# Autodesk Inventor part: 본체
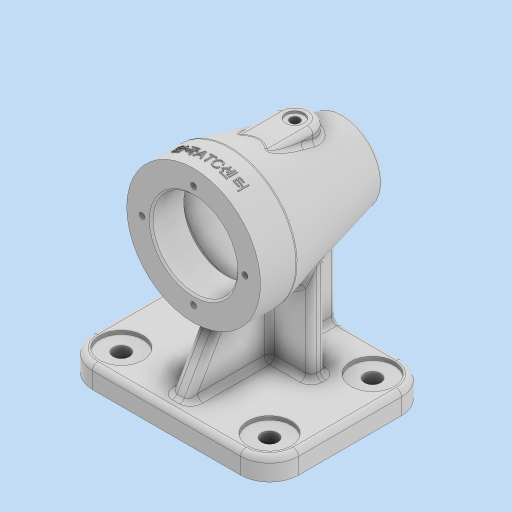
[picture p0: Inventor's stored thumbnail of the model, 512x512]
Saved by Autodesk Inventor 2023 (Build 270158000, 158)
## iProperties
Created: 2024-12
Part Number: 본체
Material: 일반
Document SubType Name: Modeling
Designer: asung
Density: 1 g/cm^3
Appearance: 기본값
Author: asung
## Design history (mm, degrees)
sketch "스케치1"
  geometry: L1 (-5744.5, -45.233)-(-5744.5, 45.233); L2 (5744.5, 45.233)-(5744.5, -45.233); L3 (41, -44.5)-(-41, -44.5); L4 (-57, -28.5)-(-57, 28.5); L5 (-41, 44.5)-(41, 44.5); L6 (57, 28.5)-(57, -28.5); L7 (57, -44.5)-(-57, 44.5); L8 (-57, -44.5)-(57, 44.5); A1 r 16 centre (41, -28.5) between (41, -44.5) and (57, -28.5); A2 r 16 centre (-41, -28.5) between (-57, -28.5) and (-41, -44.5); A3 r 16 centre (-41, 28.5) between (-41, 44.5) and (-57, 28.5); A4 r 16 centre (41, 28.5) between (57, 28.5) and (41, 44.5); 1 further point
  constraints: 16 end point, 8 point on circle, 8 point on line, 8 tangent, 4 centre point, 3 equal radius, 3 parallel, 2 midpoint, 1 horizontal, 1 perpendicular
  dimensions: "d1" = 114 distance of L7.end L8.end; "d2" = 89 distance of L8.start L7.end; "d3" = 16 radius of A1
extrude "돌출1" new body sketch "스케치1" distance "d4" = 12; taper "d5" = 0 deg
sketch "스케치2"
  geometry: A1 r 16 centre (41, -28.5) between (41, -44.5) and (57, -28.5) reference; A2 r 16 centre (41, 28.5) between (57, 28.5) and (41, 44.5) reference; A3 r 16 centre (-41, 28.5) between (-41, 44.5) and (-57, 28.5) reference; A4 r 16 centre (-41, -28.5) between (-57, -28.5) and (-41, -44.5) reference; 1 further point
hole "구멍1" sketch "스케치2" at (-41, 28.5), (-41, -28.5), (41, -28.5), (41, 28.5) diameter "d6" = 9; stored, may be unused: countersink angle "d10" = 90 deg, drill point angle "d12" = 0 deg; dims "d7" = 6, "d8" = 24, "d9" = 2, "d11" = 12
node "작업 평면1"
sketch "스케치4"
  geometry: L1 (73, 12)-(73, 0) reference; L2 (73, 0)-(-16, 0) reference; L3 (-16, 0)-(-16, 12) reference; L4 (-16, 12)-(73, 12) reference; L5 (73, 0)-(57, 0) reference; L6 (58, 82)-(58, 0); L7 (58, 82)-(-26, 82); L8 (-26, 82)-(-26, 103); L9 (58, 82)-(58, 119); L10 (58, 119)-(38, 119); L11 (38, 119)-(-26, 103); 1 further point
  constraints: 12 end point, 3 vertical, 2 horizontal
  dimensions: "d23" = 82 distance of L6.start L6.end; "d24" = 15 distance of L1.end L6.end; "d25" = 0 vertical distance of L1.end L6.end; "d26" = 84 distance of L6.start L7.end; "d29" = 37 distance of L6.start L9.end; "d30" = 20 distance of L9.end L10.end; "d118" = 42 diameter of L8.end L7
revolve "회전1" sketch "스케치4" stored, may be unused: angle "d32" = 90 deg
node "작업 평면2"
sketch "스케치5"
  geometry: L1 (-16.733, 29.5)-(16.733, 29.5) reference; L2 (16.733, 29.5)-(16.733, 9.5) reference; L3 (-16.733, 9.5)-(-16.733, 29.5) reference; L4 (-21, -54.5)-(21, -54.5) reference; L5 (-37, 9.5)-(37, 9.5) reference; L6 (-37, 9.5)-(37, 9.5) reference; L7 (-37, 29.5)-(37, 29.5) reference; L8 (-37, 29.5)-(37, 29.5) reference; L9 (0, 29.5)-(0, -26.5); L10 (10, -26.5)-(10, 4.324); L11 (-10, -26.5)-(-10, 7.832); L12 (-10, 7.832)-(10, 7.832); L13 (10, 7.832)-(10, 4.324); A1 r 10 centre (0, -26.5) between (10, -26.5) and (-10, -26.5); 3 further points
  constraints: 10 end point, 2 perpendicular, 2 point on circle, 2 tangent, 2 vertical, 1 centre point, 1 coincident, 1 midpoint, 1 parallel, 1 point on line, 1 other
  dimensions: "d35" = 56 distance of L9.start L9.end; "d36" = 20 diameter of A1
extrude "돌출2" join sketch "스케치5" stored distance "d37" = 12; taper "d38" = 0 deg
sketch "스케치6"
  geometry: L1 (58, 119)-(58, 45) reference; L2 (58, 45)-(38, 45) reference; L3 (38, 45)-(-26, 61) reference; L4 (-26, 61)-(-26, 103) reference; L5 (-26, 103)-(-8, 107.5) reference; L6 (-8, 107.5)-(-8, 115) reference; L7 (-8, 115)-(22, 115) reference; L8 (22, 115)-(38, 119) reference; L9 (38, 119)-(58, 119) reference; L10 (-16, 0)-(-16, 12) reference; L11 (-16, 12)-(73, 12) reference; L12 (73, 12)-(73, 0) reference; L13 (73, 0)-(-16, 0) reference; L14 (-16, 0)-(-16, 12) reference; L15 (-16, 12)-(-16, 65.487); L16 (35.119, 65.487)-(66, 12); L17 (58, 119)-(58, 45) reference; L18 (-26, 61)-(-26, 103) reference; L19 (-26, 103)-(-8, 107.5) reference; L20 (-8, 107.5)-(-8, 115) reference; L21 (-8, 115)-(22, 115) reference; L22 (38, 119)-(58, 119) reference; L23 (-16, 0)-(-16, 12) reference; L24 (-16, 12)-(73, 12) reference; L25 (73, 12)-(73, 0) reference; L26 (73, 0)-(-16, 0) reference; L27 (-16, 65.487)-(35.119, 65.487); L28 (22, 115)-(38, 119) reference; 2 further points; 2 other entities
  constraints: 6 end point, 1 horizontal, 1 point on line, 1 vertical, 2 other
  dimensions: "d39" = 7 distance from line of L12 L16.end; "d40" = 60 deg angle of L11 L16; "d41" = 65.48678 distance between parallel lines of L13 L27
extrude "돌출3" join sketch "스케치6" stored distance "d42" = 10; taper "d43" = 0 deg
node "작업 평면3"
sketch "스케치7"
  geometry: L1 (51, 115)-(51, 111.079) reference; L2 (46, 51.659)-(46, 12) reference; L3 (46, 12)-(98, 12) reference; L4 (98, 12)-(98, 0) reference; L5 (98, 0)-(-16, 0) reference; L6 (-16, 0)-(-16, 12) reference; L7 (-16, 12)-(36, 12) reference; L8 (36, 12)-(36, 51.659) reference; L9 (31, 111.079)-(31, 115) reference; L10 (31, 115)-(51, 115) reference; L11 (69, 69.289)-(69, 12); L12 (13, 69.289)-(13, 12); A1 r 30.75 centre (41, 82) between (46, 51.659) and (51, 111.079) reference; A2 r 30.75 centre (41, 82) between (31, 111.079) and (36, 51.659) reference; 1 further point
  constraints: 4 end point, 2 point on circle, 2 point on line, 2 vertical
  dimensions: "d45" = 56 distance of L12.end L11.end; "d46" = 28 horizontal distance of point (41, 0) L11.end
  node "절단 모서리 투영5"
feature "리브1" dims "d47" = 1, "d48" = 8, "d49" = 0, "d50" = 0, "d51" = 1, "d52" = 1
feature "리브2" dims "d53" = 1, "d54" = 8, "d55" = 0, "d56" = 0, "d57" = 1, "d58" = 1
sketch "스케치8"
  geometry: C1 r 37 at (0, 0) reference; 2 further points
  constraints: 1 coincident
hole "구멍2" sketch "스케치8" at (0, 0) diameter "d59" = 47; stored, may be unused: countersink angle "d63" = 90 deg, drill point angle "d65" = 0 deg; dims "d60" = 6, "d61" = 24, "d62" = 2, "d64" = 18
chamfer "모따기1" distance "d66" = 1; stored, may be unused: second distance "d67" = 2, angle "d68" = 45 deg
sketch "스케치9"
  geometry: L1 (61, -54.5)-(58.5, -44.5) reference; L2 (58.5, -44.5)-(0, -44.5) reference; L3 (0, -44.5)-(0, 44.5) reference; L4 (0, 44.5)-(12, 44.5) reference; L5 (12, 44.5)-(12, 37.5) reference; L6 (12, 37.5)-(45, 18.447) reference; L7 (45, 18.447)-(45, 29.5) reference; L8 (45, 29.5)-(57.5, 29.5) reference; L9 (57.5, 29.5)-(58.5, 28.5) reference; L10 (58.5, 28.5)-(58.5, 11.5) reference; L11 (58.5, 11.5)-(105.5, 11.5) reference; L12 (105.5, 11.5)-(105.5, 28.5) reference; L13 (105.5, 28.5)-(106.5, 29.5) reference; L14 (106.5, 29.5)-(119, 29.5) reference; L15 (119, 29.5)-(119, 9.5) reference; L16 (119, 9.5)-(115, -6.5) reference; L17 (115, -6.5)-(115, -36.5) reference; L18 (115, -36.5)-(107.5, -36.5) reference; L19 (107.5, -36.5)-(103, -54.5) reference; L20 (103, -54.5)-(61, -54.5) reference; L21 (112.793, 5.287)-(103.664, -31.228); L22 (82, -33.5)-(100.754, -33.5); L23 (105.5, 11.5)-(58.5, 11.5) reference; L24 (82, 11.5)-(82, -33.5); L25 (82, 11.5)-(107.942, 11.5); A1 r 5 centre (107.942, 6.5) between (112.793, 5.287) and (107.942, 11.5); A2 r 3 centre (100.754, -30.5) between (100.754, -33.5) and (103.664, -31.228); 3 further points
  constraints: 9 end point, 5 tangent, 4 point on circle, 3 parallel, 2 centre point, 1 midpoint
  dimensions: "d69" = 5 distance between parallel lines of L16 L21; "d70" = 45 distance between parallel lines of L11 L22; "d71" = 5 radius of A1; "d72" = 3 radius of A2
revolve "회전2" sketch "스케치9" stored, may be unused: angle "d73" = 90 deg
sketch "스케치10"
  geometry: C1 r 18.754 at (0, 0) reference; 2 further points
  constraints: 1 coincident
hole "구멍3" sketch "스케치10" at (0, 0) diameter "d74" = 31; stored, may be unused: countersink angle "d78" = 90 deg, drill point angle "d80" = 0 deg; dims "d75" = 6, "d76" = 35, "d77" = 10, "d79" = 13
fillet "모깎기1" dims "d81" = 0.3
sketch "스케치11" dims "d82" = 57
  geometry: C1 r 37 at (0, 0) reference; C2 r 24.5 at (0, 0) reference; 3 further points
  constraints: 2 vertical alignment, 1 coincident, 2 other
hole "구멍4" sketch "스케치11" at (0, 28.5) diameter "d83" = 3.242; stored, may be unused: countersink angle "d87" = 90 deg, drill point angle "d89" = 118 deg; dims "d84" = 8, "d85" = 35, "d86" = 10, "d88" = 10
sketch "스케치12"
  geometry: C1 r 5 at (0, 26.5); A1 r 10 centre (0, 26.5) between (10, 26.5) and (-10, 26.5) reference; 1 further point
  constraints: 1 centre point, 1 coincident
  dimensions: "d93" = 10 diameter of C1
extrude "돌출4" cut sketch "스케치12" distance "d94" = 1; taper "d95" = 0 deg
sketch "스케치13"
  geometry: C1 r 5 at (0, 0) reference; 2 further points
  constraints: 1 coincident
hole "구멍5" sketch "스케치13" at (0, 0) diameter "d96" = 5.1881; stored, may be unused: countersink angle "d100" = 90 deg, drill point angle "d102" = 118 deg; dims "d97" = 20, "d98" = 4, "d99" = 2, "d101" = 25
node "작업 평면4"
sketch "스케치14"
  geometry: L1 (-37, 10)-(37, 10) reference; L2 (5, -10)-(5, -1.249) reference; L3 (-5, -1.249)-(-5, -10) reference; L4 (5, -10)-(-5, -10) reference; 4 further points; 1 other entity
  constraints: 1 midpoint, 1 vertical alignment, 2 other
  dimensions: "d103" = 9 distance of point (0, 10) point (0, 1)
feature "엠보싱1" sketch "스케치14" dims "d104" = 0.5, "d105" = 0
fillet "모깎기4" dims "d108" = 3
fillet "모깎기5" dims "d109" = 3
fillet "모깎기6" dims "d110" = 3
fillet "모깎기9" dims "d113" = 3
fillet "모깎기10" dims "d114" = 3
fillet "모깎기11" dims "d115" = 3
fillet "모깎기12" dims "d116" = 3
fillet "모깎기13" dims "d117" = 3
node "작업 평면5"
sketch "스케치15"
  geometry: L1 (23.5, 28.5)-(24.5, 29.5) reference; L2 (24.5, 29.5)-(26.879, 29.5) reference; L3 (26.879, 29.5)-(26.879, 19.5) reference; L4 (26.879, 19.5)-(28.5, 18.526) reference; L5 (28.5, 18.526)-(30.121, 19.5) reference; L6 (30.121, 19.5)-(30.121, 29.5) reference; L7 (30.121, 29.5)-(37, 29.5) reference; L8 (37, 29.5)-(37, 9.869) reference; L9 (36.91, 9.142)-(21, -54.5) reference; L10 (-21, -54.5)-(-36.91, 9.142) reference; L11 (-37, 9.869)-(-37, 29.5) reference; L12 (-37, 29.5)-(-30.121, 29.5) reference; L13 (-30.121, 29.5)-(-30.121, 19.5) reference; L14 (-30.121, 19.5)-(-28.5, 18.526) reference; L15 (-28.5, 18.526)-(-26.879, 19.5) reference; L16 (-26.879, 19.5)-(-26.879, 29.5) reference; L17 (-26.879, 29.5)-(-24.5, 29.5) reference; L18 (-24.5, 29.5)-(-23.5, 28.5) reference; L19 (-23.5, 28.5)-(-23.5, 11.5) reference; L20 (-23.5, 11.5)-(-25.942, 11.5) reference; L21 (-30.793, 5.287)-(-21.664, -31.228) reference; L22 (-18.754, -33.5)-(-17.5, -33.5) reference; L23 (-17.5, -33.5)-(-17.5, -43.2) reference; L24 (-17.2, -43.5)-(-15.5, -43.5) reference; L25 (-12.5, -46.5)-(12.5, -46.5) reference; L26 (15.5, -43.5)-(17.2, -43.5) reference; L27 (17.5, -43.2)-(17.5, -33.5) reference; L28 (17.5, -33.5)-(18.754, -33.5) reference; L29 (21.664, -31.228)-(30.793, 5.287) reference; L30 (25.942, 11.5)-(23.5, 11.5) reference; L31 (23.5, 11.5)-(23.5, 28.5) reference; L32 (21, -54.5)-(-21, -54.5) reference; A1 r 3 centre (34, 9.869) between (36.91, 9.142) and (37, 9.869) reference; A2 r 3 centre (-34, 9.869) between (-37, 9.869) and (-36.91, 9.142) reference; A3 r 5 centre (-25.942, 6.5) between (-25.942, 11.5) and (-30.793, 5.287) reference; A4 r 3 centre (-18.754, -30.5) between (-21.664, -31.228) and (-18.754, -33.5) reference; A5 r 0.3 centre (-17.2, -43.2) between (-17.5, -43.2) and (-17.2, -43.5) reference; A6 r 3 centre (-12.5, -43.5) between (-15.5, -43.5) and (-12.5, -46.5) reference; A7 r 3 centre (12.5, -43.5) between (12.5, -46.5) and (15.5, -43.5) reference; A8 r 0.3 centre (17.2, -43.2) between (17.2, -43.5) and (17.5, -43.2) reference; A9 r 3 centre (18.754, -30.5) between (18.754, -33.5) and (21.664, -31.228) reference; A10 r 5 centre (25.942, 6.5) between (30.793, 5.287) and (25.942, 11.5) reference; 1 further point
  node "절단 모서리 투영7"
sketch "스케치16"
  geometry: L1 (23.5, 28.5)-(24.5, 29.5) reference; L2 (24.5, 29.5)-(26.879, 29.5) reference; L3 (26.879, 29.5)-(26.879, 19.5) reference; L4 (26.879, 19.5)-(28.5, 18.526) reference; L5 (28.5, 18.526)-(30.121, 19.5) reference; L6 (30.121, 19.5)-(30.121, 29.5) reference; L7 (30.121, 29.5)-(37, 29.5) reference; L8 (37, 29.5)-(37, 9.869) reference; L9 (36.91, 9.142)-(21, -54.5) reference; L10 (21, -54.5)-(-21, -54.5) reference; L11 (-21, -54.5)-(-36.91, 9.142) reference; L12 (-37, 9.869)-(-37, 29.5) reference; L13 (-37, 29.5)-(-30.121, 29.5) reference; L14 (-30.121, 29.5)-(-30.121, 19.5) reference; L15 (-30.121, 19.5)-(-28.5, 18.526) reference; L16 (-28.5, 18.526)-(-26.879, 19.5) reference; L17 (-26.879, 19.5)-(-26.879, 29.5) reference; L18 (-26.879, 29.5)-(-24.5, 29.5) reference; L19 (-24.5, 29.5)-(-23.5, 28.5) reference; L20 (-23.5, 28.5)-(-23.5, 11.5) reference; L21 (-23.5, 11.5)-(-25.942, 11.5) reference; L22 (-30.793, 5.287)-(-21.664, -31.228) reference; L23 (-18.754, -33.5)-(-17.5, -33.5) reference; L24 (-17.5, -33.5)-(-17.5, -43.2) reference; L25 (-17.2, -43.5)-(-15.5, -43.5) reference; L26 (-12.5, -46.5)-(12.5, -46.5) reference; L27 (15.5, -43.5)-(17.2, -43.5) reference; L28 (17.5, -43.2)-(17.5, -33.5) reference; L29 (17.5, -33.5)-(18.754, -33.5) reference; L30 (21.664, -31.228)-(30.793, 5.287) reference; L31 (25.942, 11.5)-(23.5, 11.5) reference; L32 (23.5, 11.5)-(23.5, 28.5) reference; A1 r 3 centre (34, 9.869) between (36.91, 9.142) and (37, 9.869) reference; A2 r 3 centre (-34, 9.869) between (-37, 9.869) and (-36.91, 9.142) reference; A3 r 5 centre (-25.942, 6.5) between (-25.942, 11.5) and (-30.793, 5.287) reference; A4 r 3 centre (-18.754, -30.5) between (-21.664, -31.228) and (-18.754, -33.5) reference; A5 r 0.3 centre (-17.2, -43.2) between (-17.5, -43.2) and (-17.2, -43.5) reference; A6 r 3 centre (-12.5, -43.5) between (-15.5, -43.5) and (-12.5, -46.5) reference; A7 r 3 centre (12.5, -43.5) between (12.5, -46.5) and (15.5, -43.5) reference; A8 r 0.3 centre (17.2, -43.2) between (17.2, -43.5) and (17.5, -43.2) reference; A9 r 3 centre (18.754, -30.5) between (18.754, -33.5) and (21.664, -31.228) reference; A10 r 5 centre (25.942, 6.5) between (30.793, 5.287) and (25.942, 11.5) reference; 1 further point
  dimensions: "d120" = 42 distance of L10.end L9.end (derived)
  node "절단 모서리 투영8"
fillet "모깎기14" dims "d121" = 3
feature "ӿ耀ԁ耀ԃ耀ԅ耀ԇ耀ԉ耀ԋ耀ԍ耀" dims "d1" = 114, "d2" = 89, "d3" = 16, "d4" = 12, "d5" = 0, "d6" = 9, "d7" = 6, "d8" = 24, "d9" = 2, "d10" = 90 deg, "d11" = 12, "d12" = 0, "d23" = 82, "d24" = 15, "d25" = 0, "d26" = 84, "d29" = 37, "d30" = 20, "d32" = 90 deg, "d33" = -115, "d35" = 56, "d36" = 20, "d37" = 12, "d38" = 0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
node "솔리드1"
pattern_circular "원형 패턴1" dims angle "d91" = 360 deg
node "투영된 루프1"
node "투영된 루프2"
node "투영된 루프3"
node "절단 모서리 투영1"
node "절단 모서리 투영2"
node "절단 모서리 투영3"
node "절단 모서리 투영4"
node "절단 모서리 투영6"
feature "A9D066F2-1C7D-4E18-AEED-F7BC21143FA4" dims "d6" = 9, "d7" = 6, "d8" = 24, "d9" = 2, "d10" = 90 deg, "d11" = 12, "d12" = 0
